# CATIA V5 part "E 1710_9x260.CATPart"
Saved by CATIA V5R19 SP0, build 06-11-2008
Nomenclature: E 1710_9x260
Description: PART-E 1710_9x260-DESC
Property "Hersteller": "Meusburger"
Property "Material": "1.2210"
Property "Bestellnummer": "E 1710/9x260"
Property "Teilenummer": "E 1710/9x260"
Property "Beschreibung": "Auswerferstift gehärtet _ Ejector pin, through-hardened"
Material "Steel": density 7860 kg/m3, Young's modulus 2e+11 Pa, Poisson ratio 0.266, thermal expansion 1.17e-05 1/K
Bounding box of the stored display mesh (mm): x -7 to 7, y -7 to 7, z 0 to 260
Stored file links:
  G:\UTB\Kombinované\Bakalářská práce\Catia\FORMA\E 1710_9x260.CATPart
  D:\Aplikace\CATIA\Nová složka\win_b64\startup\materials\Catalog.CATMaterial
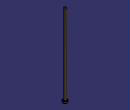
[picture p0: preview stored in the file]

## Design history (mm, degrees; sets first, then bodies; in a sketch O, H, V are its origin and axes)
Body1 "E 1710_9x260" (main body)
  Solid1: solid without history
